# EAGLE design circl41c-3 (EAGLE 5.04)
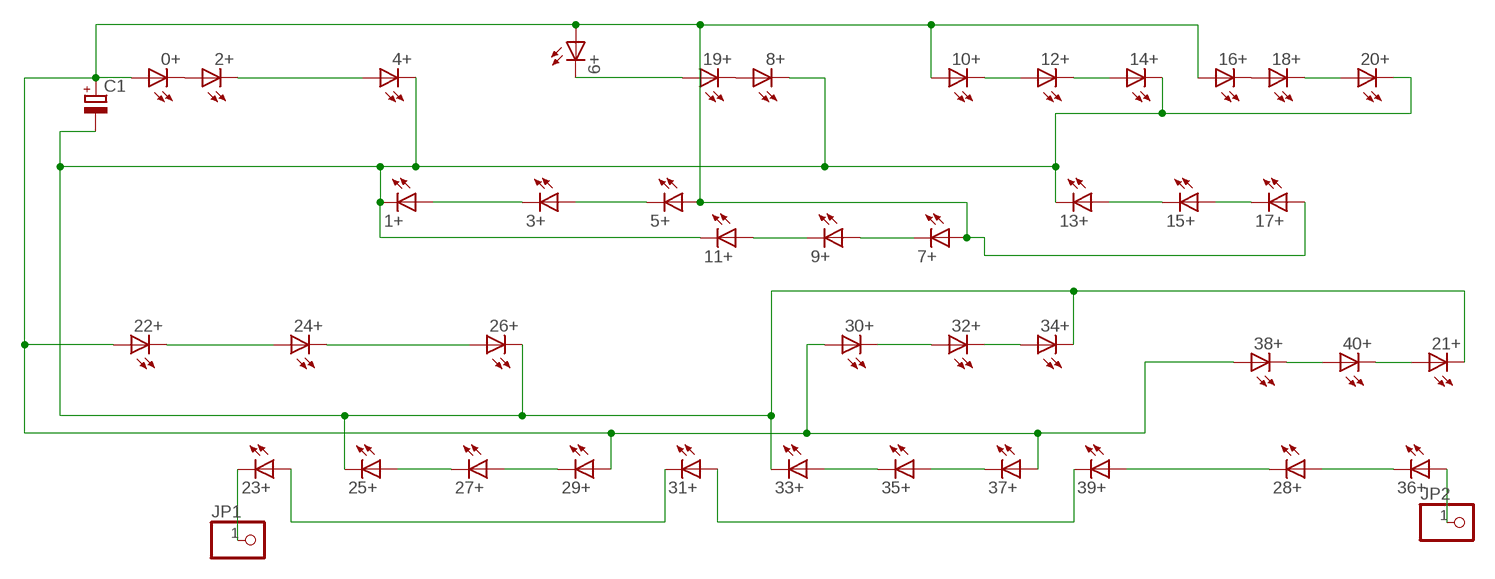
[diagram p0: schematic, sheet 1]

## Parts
0+  LED5MM  [LED5MM]
1+  LED5MM  [LED5MM]
2+  LED5MM  [LED5MM]
3+  LED5MM  [LED5MM]
4+  LED5MM  [LED5MM]
5+  LED5MM  [LED5MM]
6+  LED5MM  [LED5MM]
7+  LED5MM  [LED5MM]
8+  LED5MM  [LED5MM]
9+  LED5MM  [LED5MM]
10+  LED5MM  [LED5MM]
11+  LED5MM  [LED5MM]
12+  LED5MM  [LED5MM]
13+  LED5MM  [LED5MM]
14+  LED5MM  [LED5MM]
15+  LED5MM  [LED5MM]
16+  LED5MM  [LED5MM]
17+  LED5MM  [LED5MM]
18+  LED5MM  [LED5MM]
19+  LED5MM  [LED5MM]
20+  LED5MM  [LED5MM]
21+  LED5MM  [LED5MM]
22+  LED5MM  [LED5MM]
23+  LED5MM  [LED5MM]
24+  LED5MM  [LED5MM]
25+  LED5MM  [LED5MM]
26+  LED5MM  [LED5MM]
27+  LED5MM  [LED5MM]
28+  LED5MM  [LED5MM]
29+  LED5MM  [LED5MM]
30+  LED5MM  [LED5MM]
31+  LED5MM  [LED5MM]
32+  LED5MM  [LED5MM]
33+  LED5MM  [LED5MM]
34+  LED5MM  [LED5MM]
35+  LED5MM  [LED5MM]
36+  LED5MM  [LED5MM]
37+  LED5MM  [LED5MM]
38+  LED5MM  [LED5MM]
39+  LED5MM  [LED5MM]
40+  LED5MM  [LED5MM]
C1  CPOL-EUE7.5-16  [E7,5-16]
JP1  PINHD-1X1M  [1X01M]
JP2  PINHD-1X1M  [1X01M]

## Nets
MINUS: 1+.K(C) 4+.K(C) 8+.K(C) 11+.K(C) 13+.K(C) 14+.K(C) 20+.K(C) 21+.K(C) 25+.K(C) 26+.K(C) 33+.K(C) 34+.K(C) C1.-
N$1: 31+.A 39+.K(C)
N$2: 28+.K(C) 39+.A
N$3: 28+.A 36+.K(C)
N$4: 23+.K(C) JP1.1
N$5: 36+.A JP2.1
N$6: 35+.A 37+.K(C)
N$7: 33+.A 35+.K(C)
N$8: 27+.A 29+.K(C)
N$9: 25+.A 27+.K(C)
N$12: 23+.A 31+.K(C)
N$13: 38+.K(C) 40+.A
N$14: 32+.K(C) 34+.A
N$15: 30+.K(C) 32+.A
N$16: 3+.A 5+.K(C)
N$17: 1+.A 3+.K(C)
N$18: 21+.A 40+.K(C)
N$20: 22+.K(C) 24+.A
N$21: 24+.K(C) 26+.A
N$22: 7+.K(C) 9+.A
N$23: 9+.K(C) 11+.A
N$24: 13+.A 15+.K(C)
N$25: 15+.A 17+.K(C)
N$28: 18+.K(C) 20+.A
N$29: 16+.K(C) 18+.A
N$30: 10+.K(C) 12+.A
N$31: 12+.K(C) 14+.A
N$33: 6+.K(C) 19+.A
N$34: 8+.A 19+.K(C)
N$35: 2+.K(C) 4+.A
N$36: 0+.K(C) 2+.A
PLUS: 0+.A 5+.A 6+.A 7+.A 10+.A 16+.A 17+.A 22+.A 29+.A 30+.A 37+.A 38+.A C1.+

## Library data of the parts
0+ 1+ 2+ 3+ 4+ 5+ 6+ 7+ 8+ 9+ 10+ 11+ 12+ 13+ 14+ 15+ 16+ 17+ 18+ 19+ 20+ 21+ 22+ 23+ 24+ 25+ 26+ 27+ 28+ 29+ 30+ 31+ 32+ 33+ 34+ 35+ 36+ 37+ 38+ 39+ 40+ = led(2):LED: LED
C1 = rcl-2:CPOL-EU: POLARIZED CAPACITOR, European symbol
JP1 JP2 = pinhead(2):PINHD-1X1: PIN HEADER

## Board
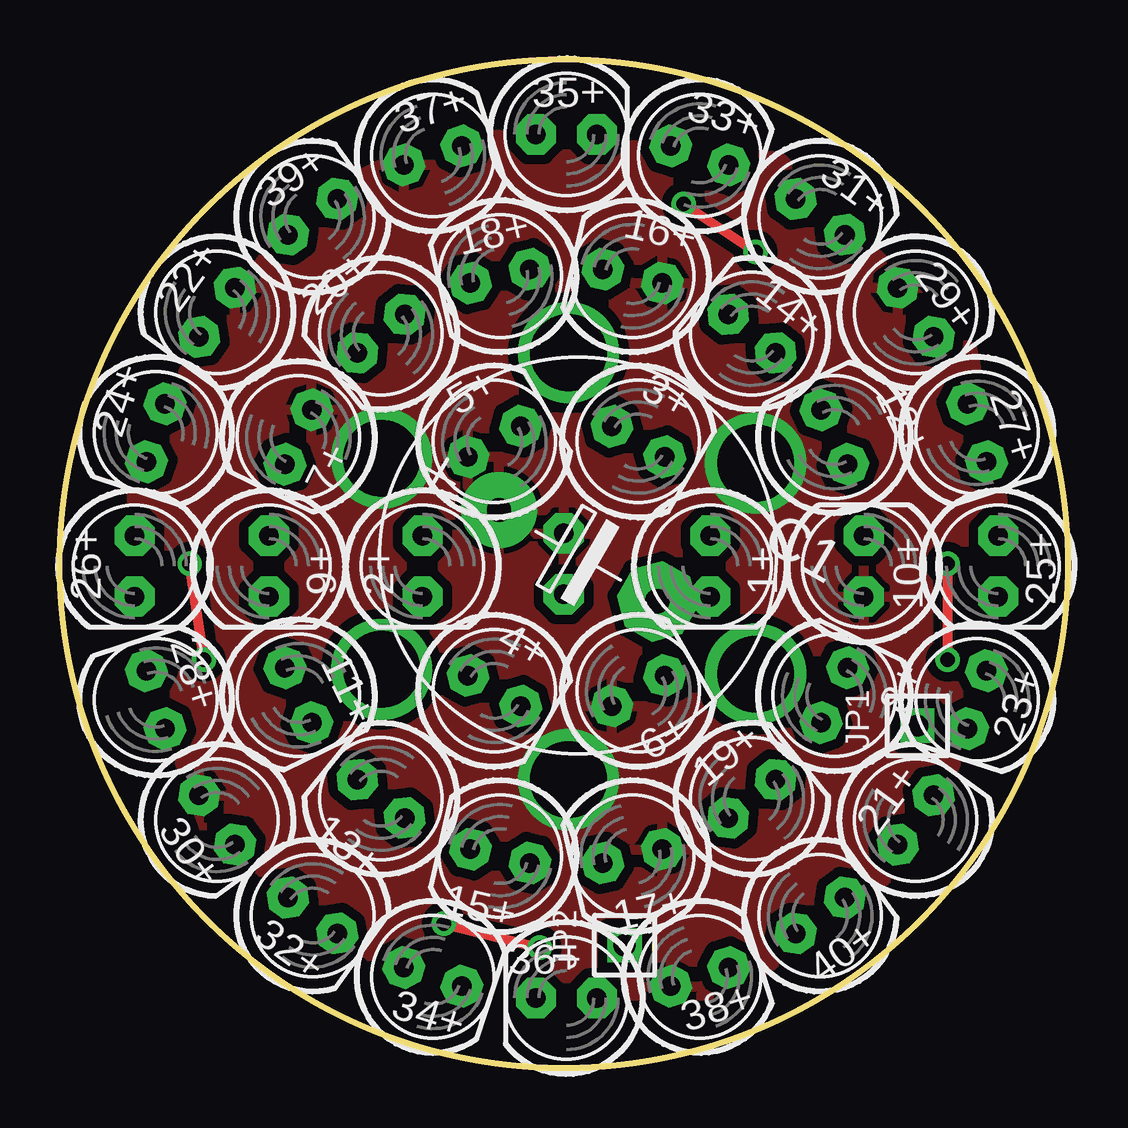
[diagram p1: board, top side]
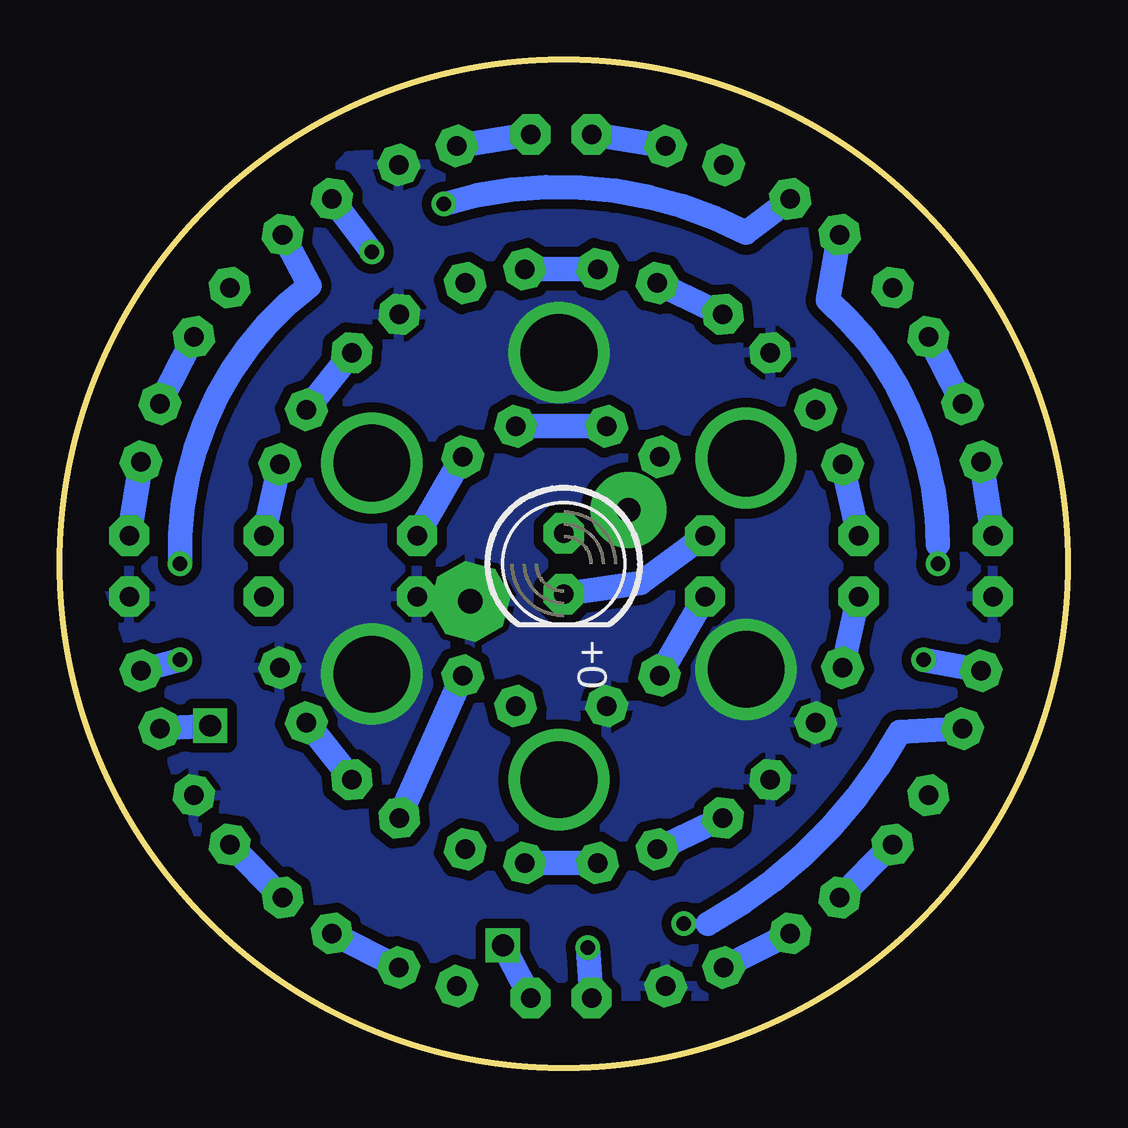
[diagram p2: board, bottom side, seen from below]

Size 42 x 42 mm. Coordinates in mm from the lower left corner, seen from the top.
Outline: circle at 21,21 radius 21
Copper layers (1*16): Top 0.035mm / dielectric 1.5mm / Bottom 0.035mm
Design rules "default": minimum track width 10mil, minimum drill 24mil, track to track 8mil, track to pad 8mil, pad to pad 8mil, via to via 8mil, smd to smd 8mil, copper to edge 40mil, drill to drill 8mil, minimum pad ring 10mil, minimum via ring 8mil, stop-mask expansion 4mil, vias tented up to drill 0mil, thermal gap 10mil

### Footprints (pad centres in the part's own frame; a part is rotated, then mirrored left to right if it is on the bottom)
LED5MM = drill 0.813 pad 1.676 octagon: A -1.27,0; K 1.27,0
E7,5-16 = drill 1.016 pad 3.15 round: + -3.81,0 | drill 1.016 pad 3.15 octagon: - 3.81,0
1X01M = drill 0.914 square: 1 0,0

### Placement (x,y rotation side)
0+  21,21 270 bottom
1+  27.11,20.9 270 top
2+  15.11,20.9 270 top
3+  24.11,26.1 330 top
4+  18.11,15.7 330 top
5+  18.11,26.1 30 top
6+  24.11,15.7 30 top
7+  9.94,26.28 244 top
8+  32.28,15.52 64 top
9+  8.71,20.9 270 top
10+  33.51,20.9 90 top
11+  9.94,15.52 296 top
12+  32.28,26.28 116 top
13+  13.38,11.21 141 top
14+  28.84,30.59 141 top
15+  18.35,8.81 167 top
16+  23.87,32.99 167 top
17+  23.87,8.81 193 top
18+  18.35,32.99 193 top
19+  28.84,11.21 39 top
20+  13.38,30.59 219 top
21+  35.67,10.32 54 top
22+  6.55,31.48 234 top
23+  38.23,15.34 252 top
24+  3.99,26.46 252 top
25+  39.11,20.9 270 top
26+  3.11,20.9 270 top
27+  38.23,26.46 288 top
28+  3.99,15.34 108 top
29+  35.67,31.48 306 top
30+  6.55,10.32 306 top
31+  31.69,35.46 324.1 top
32+  10.53,6.34 324.1 top
33+  26.67,38.02 342 top
34+  15.55,3.78 342 top
35+  21.11,38.9 0 top
36+  21.11,2.9 180 top
37+  15.55,38.02 17.9 top
38+  26.67,3.78 17.9 top
39+  10.53,35.46 35.9 top
40+  31.69,6.34 35.9 top
C1  21.6,21.34 330 top
JP1  35.74,14.25 0 top
JP2  23.54,5.1 0 top

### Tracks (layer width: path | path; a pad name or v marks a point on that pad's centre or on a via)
MINUS  (via drill 3.2)
  other vias: 13.4,16.6 29,16.4 21.2,29.8
  pour Bottom (isolate 0.406): 17,39 30,38 38,30 40,20 36,9 28,3 15,3 6,10 3,18 3,26 10,36 14,38
N$1  (via drill 0.6)
  Top 0.406: v26,36 v29,34
  Bottom 1.016: 39+.K 13.4,34.8 arc-44 v26,36 | v29,34 31+.A
N$2  (via drill 0.6)
  Top 0.406: v6,17 v5.4,21
  Bottom 0.406: v5.4,21 5.4,21.8
  Bottom 1.016: 5.4,21.8 arc-48 10,32 39+.A | 28+.K v6,17
N$3  (via drill 0.6)
  Top 0.406: v16,6 v20,5
  Bottom 0.406: 15,6 v16,6
  Bottom 1.016: 28+.A 7,14 arc33 15,6 | v20,5 36+.K
N$4
  Bottom 1.016: 23+.K JP1.1
N$5
  Bottom 1.016: 36+.A JP2.1
N$6
  Bottom 1.016: 37+.K 35+.A
N$7
  Bottom 1.016: 35+.K 33+.A
N$8
  Bottom 1.016: 27+.A 29+.K
N$9
  Bottom 1.016: 25+.A 27+.K
N$12  (via drill 0.6)
  Top 0.406: v37,17 v37,21
  Bottom 1.016: 31+.K 31.6,32.6 arc-55 v37,21 | v37,17 23+.A
N$13
  Bottom 1.016: 38+.K 40+.A
N$14
  Bottom 1.016: 32+.K 34+.A
N$15
  Bottom 1.016: 30+.K 32+.A
N$16
  Bottom 1.016: 5+.K 3+.A
N$17
  Bottom 1.016: 1+.A 3+.K
N$18
  Bottom 1.016: 40+.K 21+.A
N$20
  Bottom 1.016: 24+.A 22+.K
N$21
  Bottom 1.016: 26+.A 24+.K
N$22
  Bottom 1.016: 9+.A 7+.K
N$23
  Bottom 1.016: 11+.A 9+.K
N$24
  Bottom 1.016: 15+.K 13+.A
N$25
  Bottom 1.016: 15+.A 17+.K
N$28
  Bottom 1.016: 20+.A 18+.K
N$29
  Bottom 1.016: 18+.A 16+.K
N$30
  Bottom 1.016: 12+.A 10+.K
N$31
  Bottom 1.016: 14+.A 12+.K
N$33
  Bottom 1.016: 19+.A 6+.K
N$34
  Bottom 1.016: 19+.K 8+.A
N$35
  Bottom 1.016: 4+.A 2+.K
N$36
  Bottom 1.016: 0+.K 17.8,20.2 2+.A
PLUS  (via drill 3.2)
  other vias: 21.2,12 13.4,25.4 29,25.2
  pour Top (isolate 0.406): 17,39 30,38 38,30 40,20 36,9 28,3 15,3 6,10 3,18 3,26 10,36 14,38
